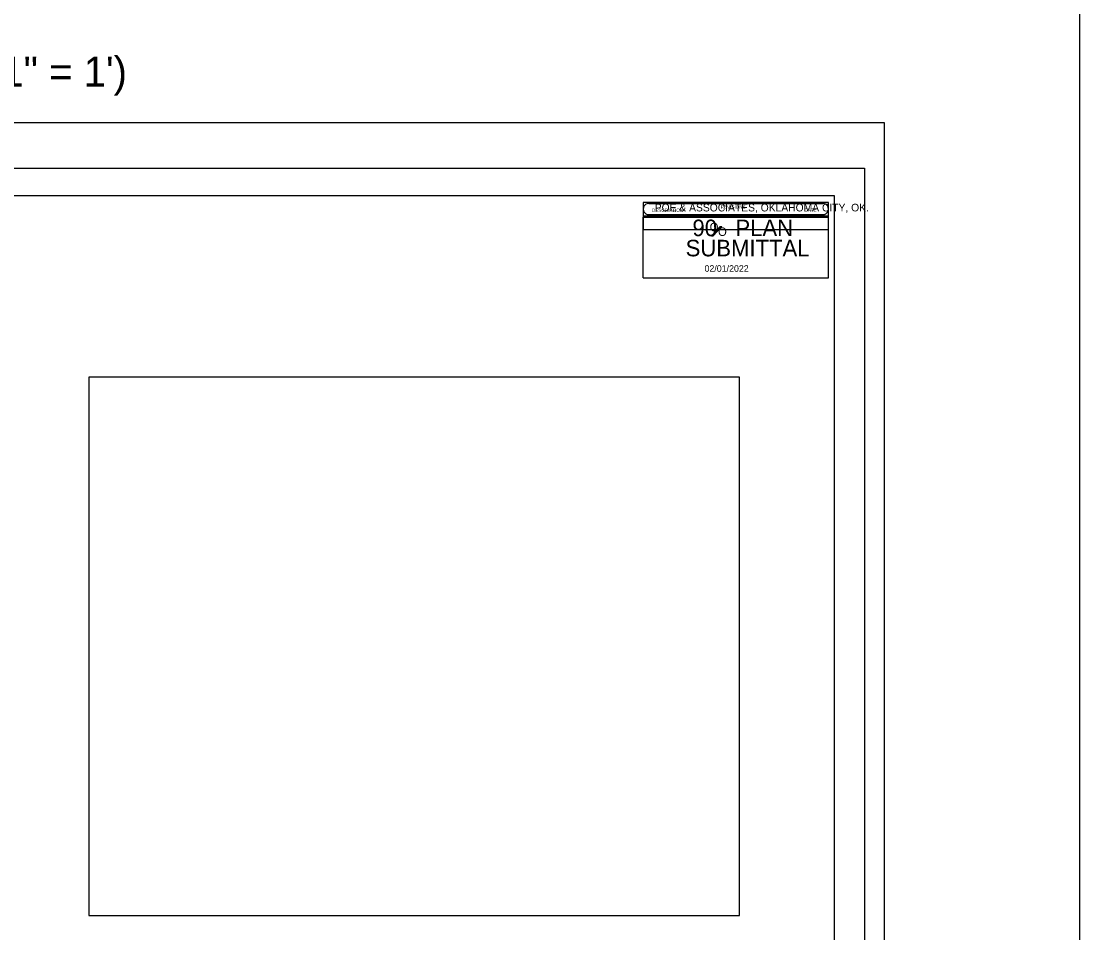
# Model space of a CAD drawing. Extents: x 12312.5 to 12355.9, y 579 to 640.5.
# Drawn here: x 12336.68 to 12355.91, y 593.88 to 610.44 of the extents above; entities that cross this region are included whole.
import ezdxf

# ---------------------------------------------------------------- set-up
doc = ezdxf.new("R2010")
doc.units = 0
for name, color, linetype in [('S', 7, 'Continuous'), ('SHT_Plot_Shape_Full', 7, 'Continuous'), ('SHT_Plot_Shape_Half', 7, 'Continuous'), ('SHT_Sheet_Border', 7, 'Continuous'), ('SHT_Stamp_90_Submit', 7, 'Continuous'), ('SHT_Stamp_Rev_Block', 7, 'Continuous'), ('T', 7, 'Continuous')]:
    doc.layers.add(name, color=color, linetype=linetype)

msp = doc.modelspace()

# ---------------------------------------------------------------- linework, layer by layer
at = {"layer": 'S'}
msp.add_lwpolyline([(12355.912, 640.488), (12312.476, 640.488), (12312.476, 579.031), (12355.912, 579.031)], close=True, dxfattribs=at)
at = {"layer": 'SHT_Plot_Shape_Full'}
msp.add_lwpolyline([(12316.36, 608.6), (12352.36, 608.6), (12352.36, 584.6), (12316.36, 584.6)], close=True, dxfattribs=at)
at = {"layer": 'SHT_Plot_Shape_Half'}
msp.add_lwpolyline([(12317.998, 607.775), (12351.998, 607.775), (12351.998, 585.775), (12317.998, 585.775)], close=True, dxfattribs=at)
at = {"layer": 'SHT_Sheet_Border'}
msp.add_lwpolyline([(12351.448, 586.275), (12319.948, 586.275), (12319.948, 607.275), (12351.448, 607.275)], close=True, dxfattribs=at)
at = {"layer": 'SHT_Stamp_90_Submit'}
for p, q in [((12348.079, 607.13), (12351.245, 607.13)), ((12347.979, 606.88), (12351.345, 606.88)), ((12347.979, 605.781), (12347.979, 606.88)), ((12348.079, 606.93), (12351.245, 606.93)), ((12351.345, 605.781), (12351.345, 606.88)), ((12349.222, 606.542), (12349.377, 606.714)), ((12349.24, 606.542), (12349.395, 606.714)), ((12349.245, 606.542), (12349.4, 606.714)), ((12349.252, 606.542), (12349.408, 606.714)), ((12349.377, 606.714), (12349.408, 606.714)), ((12349.222, 606.542), (12349.252, 606.542)), ((12347.979, 605.781), (12351.345, 605.781))]:
    msp.add_line(p, q, dxfattribs=at)
for centre, start, end in [((12348.079, 607.03), 89.9952, 270), ((12351.245, 607.03), 270, 90.0048)]:
    msp.add_arc(centre, 0.1, start, end, dxfattribs=at)
at = {"layer": 'SHT_Stamp_Rev_Block'}
for p, q in [((12347.979, 607.151), (12347.979, 606.651)), ((12351.345, 607.151), (12347.979, 607.151)), ((12351.345, 606.651), (12351.345, 607.151)), ((12351.345, 606.901), (12347.979, 606.901)), ((12351.345, 606.651), (12347.979, 606.651))]:
    msp.add_line(p, q, dxfattribs=at)
at = {"layer": 'T'}
msp.add_lwpolyline([(12337.909, 594.195), (12349.729, 594.195), (12349.729, 603.973), (12337.909, 603.973)], close=True, dxfattribs=at)

# ---------------------------------------------------------------- texts
at = {"layer": 'S'}
msp.add_text('SCALE:   1=1  (DEC. 1" = 1\')', height=0.54513, dxfattribs=at).set_placement((12329.289, 609.255))
at = {"layer": 'SHT_Stamp_90_Submit'}
for s, height, p in [('POE & ASSOCIATES, OKLAHOMA CITY, OK.', 0.14, (12348.189, 606.987)), ('90   PLAN', 0.3, (12348.874, 606.538)), ('O', 0.153, (12349.187, 606.627)), ('O', 0.153, (12349.339, 606.542)), ('SUBMITTAL', 0.3, (12348.75, 606.171)), ('02/01/2022', 0.12, (12349.093, 605.89))]:
    msp.add_text(s, height=height, rotation=360, dxfattribs=at).set_placement(p)
at = {"layer": 'SHT_Stamp_Rev_Block'}
for s, p in [('DESCRIPTION', (12348.139, 606.979)), ('REVISIONS', (12349.388, 607.038)), ('DATE', (12350.908, 606.983))]:
    msp.add_text(s, height=0.06, dxfattribs=at).set_placement(p)

doc.saveas('drawing.dxf')
